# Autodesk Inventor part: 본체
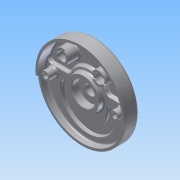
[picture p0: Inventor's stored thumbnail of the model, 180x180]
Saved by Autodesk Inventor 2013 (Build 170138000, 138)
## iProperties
Created: 2015-05
Part Number: 본체
Material: 알루미늄 6061
Document SubType Name: Modeling
Designer: Administrator
Density: 2.71 g/cm^3
Mass: 1042.94 g
Surface Area: 1023.38 cm^2
Volume: 384.847 cm^3
Author: Administrator
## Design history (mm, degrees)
sketch "스케치1"
  geometry: C1 r 95 at (0, 0); 1 further point
  constraints: 1 centre point, 1 coincident
  dimensions: "d0" = 190 diameter of C1
extrude "돌출1" new body sketch "스케치1" distance "d2" = 32; taper "d3" = 0 deg
sketch "스케치3"
  geometry: L1 (-101, 52)-(108, 52); L2 (-94.239, 12)-(94.239, 12); C1 r 15 at (-40, 52); C2 r 15 at (40, 52); A1 r 95 centre (0, 0) between (-94.239, 12) and (94.239, 12) reference; A2 r 90 centre (0, 0) between (-89.196, 12) and (89.196, 12); A3 r 42 centre (0, 0) between (40.249, 12) and (-40.249, 12)
  constraints: 6 point on circle, 6 point on line, 4 centre point, 4 end point, 2 coincident, 1 equal radius, 1 horizontal, 1 parallel
  dimensions: "d7" = 180 diameter of A2; "d9" = 52 distance from line of A1.centre L1; "d10" = 84 diameter of A3; "d11" = 12 distance from line of A1.centre L2; "d20" = 30 diameter of C1; "d22" = 40 horizontal distance of C1.centre A1.centre; "d23" = 40 horizontal distance of C2.centre A1.centre
extrude "돌출3" cut sketch "스케치3" distance "d14" = 25; taper "d15" = 0 deg
extrude "돌출4" cut sketch "스케치3" distance "d18" = 18; taper "d19" = 0 deg
sketch "스케치5"
  geometry: C1 r 15 at (-40, 52); C2 r 15 at (40, 52); A1 r 42 centre (0, 0) between (40.249, 12) and (-40.249, 12) reference
  constraints: 2 centre point, 1 equal radius, 1 horizontal alignment
  dimensions: "d24" = 30 diameter of C1; "d26" = 40 horizontal distance of A1.centre C1.centre; "d27" = 40 horizontal distance of C2.centre A1.centre; "d28" = 52 vertical distance of A1.centre C2.centre
extrude "돌출5" join sketch "스케치5" stored distance "d29" = 8; taper "d30" = 0 deg
sketch "스케치6"
  geometry: C1 r 95 at (0, 0) reference
hole "구멍1" diameter "d33" = 20; stored, may be unused: countersink angle "d37" = 90 deg, drill point angle "d39" = 0 deg; dims "d31" = 10, "d32" = 10, "d34" = 6, "d35" = 4, "d36" = 2, "d38" = 8
hole "구멍2" diameter "d42" = 20; stored, may be unused: countersink angle "d46" = 90 deg, drill point angle "d48" = 0 deg; dims "d40" = 10, "d41" = 10, "d43" = 6, "d44" = 4, "d45" = 2, "d47" = 8
sketch "스케치7"
  geometry: L1 (-6, 13.748)-(-6, -13.748); L2 (6, 13.748)-(6, -13.748); C1 r 10 at (0, 0) reference; A1 r 15 centre (0, 0) between (-6, 13.748) and (-6, -13.748) reference; 1 further point
  constraints: 4 end point, 4 point on circle, 1 parallel, 1 vertical
  dimensions: "d49" = 6 distance from line of C1.centre L1; "d50" = 6 distance from line of L2 C1.centre
extrude "돌출7" cut sketch "스케치7" distance "d53" = 3; taper "d54" = 0 deg
sketch "스케치8"
  geometry: L1 (-13.748, 6)-(13.748, 6); L2 (-13.748, -6)-(13.748, -6); C1 r 10 at (0, 0) reference; A1 r 15 centre (0, 0) between (-13.748, 6) and (13.748, 6) reference; 1 further point
  constraints: 4 end point, 4 point on circle, 1 horizontal, 1 parallel
  dimensions: "d55" = 6 distance from line of L1 C1.centre; "d56" = 6 distance from line of L2 C1.centre
extrude "돌출8" cut sketch "스케치8" distance "d57" = 3; taper "d58" = 0 deg
sketch "스케치9"
  geometry: C1 r 35 at (0, 0); A1 r 90 centre (0, 0) between (-89.196, 12) and (89.196, 12) reference
  constraints: 1 centre point, 1 coincident
  dimensions: "d59" = 70 diameter of C1
extrude "돌출9" join sketch "스케치9" distance "d61" = 10; taper "d62" = -10 deg
sketch "스케치17"
  geometry: C1 r 95 at (0, 0) reference; C2 r 26 at (0, 0)
  constraints: 1 centre point, 1 coincident
  dimensions: "d156" = 52 diameter of C2
extrude "돌출17" join sketch "스케치17" distance "d158" = 12; taper "d159" = -15 deg
hole "구멍3" diameter "d65" = 23; stored, may be unused: countersink angle "d69" = 90 deg, drill point angle "d71" = 0 deg; dims "d63" = 10, "d64" = 10, "d66" = 6, "d67" = 50, "d68" = 15, "d70" = 8
sketch "스케치13"
  geometry: L1 (-89.658, -7.844)-(-94.638, -8.28); L2 (89.658, -7.844)-(94.638, -8.28); L3 (-123, 0)-(146, 0); A1 r 90 centre (0, 0) between (-89.658, -7.844) and (89.658, -7.844) reference; A2 r 95 centre (0, 0) between (94.638, -8.28) and (-94.638, -8.28) reference
  constraints: 6 end point, 4 point on circle, 1 horizontal, 1 point on line
  dimensions: "d113" = 170 deg angle of L2 L1; "d114" = 5 deg angle of L1 L3
sketch "스케치10"
  geometry: C1 r 35 at (0, 0) reference; C2 r 9 at (-74, 0); C3 r 9 at (74, 0)
  constraints: 2 centre point, 2 horizontal alignment, 1 equal radius
  dimensions: "d72" = 18 diameter of C2; "d74" = 74 distance of C2.centre C1.centre; "d75" = 74 distance of C3.centre C1.centre
extrude "돌출10" join sketch "스케치10" stored distance "d76" = 10; taper "d77" = 0 deg
hole "구멍4" diameter "d80" = 11; stored, may be unused: countersink angle "d84" = 90 deg, drill point angle "d86" = 0 deg; dims "d78" = 10, "d79" = 10, "d81" = 6, "d82" = 18, "d83" = 11, "d85" = 8
hole "구멍5" diameter "d89" = 11; stored, may be unused: countersink angle "d93" = 90 deg, drill point angle "d95" = 0 deg; dims "d87" = 10, "d88" = 10, "d90" = 6, "d91" = 18, "d92" = 11, "d94" = 8
sketch "스케치11"
  geometry: L1 (40.249, 12)-(89.196, 12) reference; L2 (-69.854, -19)-(69.854, -19); C1 r 35 at (0, 0) reference; A1 r 59 centre (0, -19) between (-58.704, -13.1) and (58.704, -13.1); A2 r 41 centre (0, -19) between (-40.794, -14.9) and (40.794, -14.9); A3 r 9 centre (-49.749, -14) between (-40.794, -14.9) and (-58.704, -13.1); A4 r 50 centre (0, -19) between (-49.749, -14) and (49.749, -14); A5 r 9 centre (49.749, -14) between (58.704, -13.1) and (40.794, -14.9); 1 further point
  constraints: 10 point on circle, 5 centre point, 4 coincident, 2 end point, 2 tangent, 1 midpoint, 1 parallel, 1 vertical alignment
  dimensions: "d96" = 19 distance from line of L2 C1.centre; "d97" = 59 radius of A1; "d98" = 41 radius of A2; "d100" = 5 distance from line of L2 A3.centre; "d101" = 18 diameter of A3; "d102" = 9 radial gap between concentric circles of A2 A4; "d103" = 18 diameter of A5; "d104" = 5 distance from line of L2 A5.centre
extrude "돌출12" cut sketch "스케치11" distance "d107" = 7; taper "d108" = 0 deg
extrude "돌출14" cut sketch "스케치13" distance "d117" = 5; taper "d118" = 0 deg
sketch "스케치14"
  geometry: L1 (-40.15, -40.15)-(-47.244, -47.244); L2 (40.15, -40.15)-(47.244, -47.244); C1 r 11.5 at (0, 0) reference; C2 r 95 at (0, 0) reference; A1 r 72 centre (0, 0) between (-46.97, -54.569) and (46.97, -54.569); A2 r 52 centre (0, 0) between (-33.402, -39.853) and (33.402, -39.853); A3 r 5 centre (-36.614, -43.685) between (-33.402, -39.853) and (-40.15, -40.15); A4 r 5 centre (-43.709, -50.78) between (-47.244, -47.244) and (-46.97, -54.569); A5 r 5 centre (36.614, -43.685) between (40.15, -40.15) and (33.402, -39.853); A6 r 5 centre (43.709, -50.78) between (46.97, -54.569) and (47.244, -47.244); 5 further points
  constraints: 17 point on circle, 8 tangent, 6 centre point, 6 point on line, 4 end point, 3 equal radius, 2 coincident, 1 vertical alignment
  dimensions: "d119" = 90 deg angle of L2 L1; "d120" = 72 radius of A1; "d122" = 52 radius of A2; "d123" = 5 radius of A3
extrude "돌출15" join sketch "스케치14" distance "d124" = 5; taper "d125" = 0 deg
fillet "모깎기1" dims "d126" = 5, "d127" = 3
sketch "스케치15"
  geometry: L1 (36.614, -43.685)-(43.709, -50.78) reference; L2 (-43.709, -50.78)-(-36.614, -43.685) reference; A1 r 57 centre (0, 0) between (-36.614, -43.685) and (36.614, -43.685) reference; A2 r 68 centre (0, 0) between (-44.418, -51.489) and (44.418, -51.489)
  constraints: 2 point on circle, 2 point on line, 1 centre point, 1 coincident, 1 other
  dimensions: "d132" = 68 radius of A2
feature "엠보싱1" sketch "스케치15" dims "d0" = 190, "d134" = 0.5, "d135" = 0
fillet "모깎기2" dims "d136" = 5
fillet "모깎기3" dims "d137" = 0.3
fillet "모깎기5" dims "d139" = 1
fillet "모깎기6" dims "d140" = 10
fillet "모깎기9" dims "d143" = 3
fillet "모깎기12" dims "d146" = 3
chamfer "모따기1" distance "d147" = 1; stored, may be unused: second distance "d148" = 2, angle "d149" = 45 deg
fillet "모깎기13" dims "d150" = 3
fillet "모깎기14" dims "d151" = 3
node "솔리드1"
other parameters: "d109" = 170 deg, "d130" = 136
